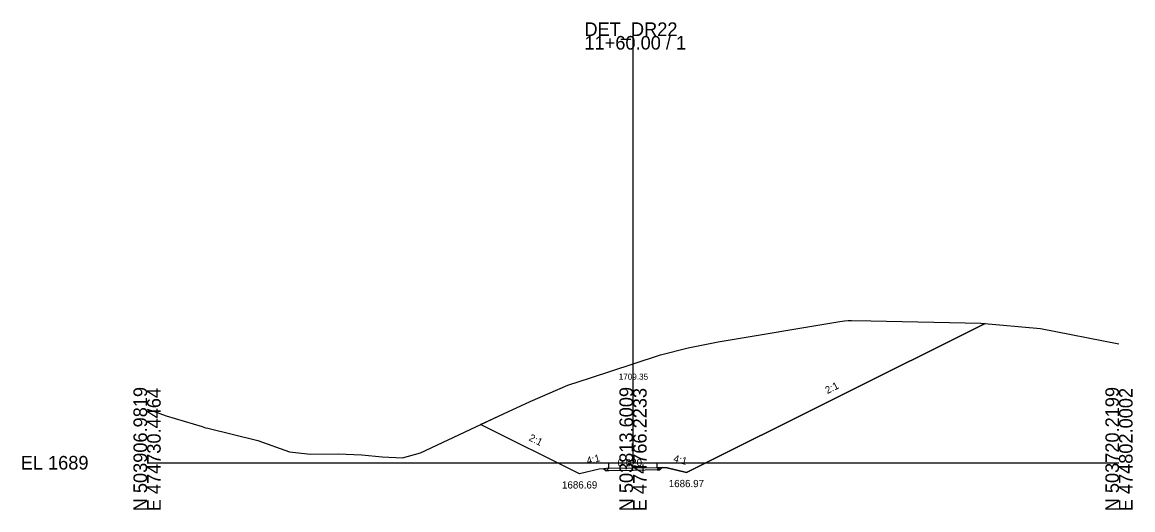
# Model space of a CAD drawing. Extents: x -26 to 1203, y -10 to 9633.
# Drawn here: x -25.7 to 202.8, y 3990.3 to 4090.7 of the extents above; entities that cross this region are included whole.
import ezdxf

# ---------------------------------------------------------------- set-up
doc = ezdxf.new("R2010")
doc.units = 0
for name, color, linetype in [('Exist Cross Section Cell', 7, 'Continuous'), ('Exist XS Center Line Elevation Label', 7, 'Continuous'), ('Exist XS Ground Line', 7, 'Continuous'), ('Prop XS Ditch Slope Text', 7, 'Continuous'), ('Prop XS Ditch Standard Text', 7, 'Continuous'), ('Prop XS Earthwork Shape', 7, 'Continuous'), ('Prop XS EOT Tick Mark', 7, 'Continuous'), ('Prop XS Finish Grade', 7, 'Continuous'), ('Prop XS Finish Grade Earthwork', 7, 'Continuous'), ('Prop XS Finish Grade Pavement', 7, 'Continuous'), ('Prop XS Pvmt Edge Slope', 7, 'Continuous'), ('Prop XS SE Text', 7, 'Continuous'), ('Prop XS Shoulder Borrow Shape', 7, 'Continuous'), ('Prop XS Side Slope Text', 7, 'Continuous'), ('Prop XS Subgrade Earthwork', 7, 'Continuous')]:
    doc.layers.add(name, color=color, linetype=linetype)

msp = doc.modelspace()

# ---------------------------------------------------------------- linework, layer by layer
at = {"layer": 'Exist Cross Section Cell'}
for p, q in [((100, 4000), (100, 4087.89)), ((0, 4000), (100, 4000)), ((100, 4000), (200, 4000))]:
    msp.add_line(p, q, dxfattribs=at)
at = {"layer": 'Exist XS Ground Line'}
msp.add_lwpolyline([(0, 4011.03), (1.34, 4010.61), (3.9, 4009.67), (11.33, 4007.45), (12.05, 4007.22), (12.5, 4007.1), (22.76, 4004.57), (29.32, 4002.26), (33.64, 4001.76), (39.29, 4001.86), (44.18, 4001.6), (48.37, 4001.21), (52.54, 4001.04), (56.3, 4002.07), (73.33, 4010.09), (78.86, 4012.58), (86.55, 4016), (91.28, 4017.51), (100, 4020.35), (105.62, 4022.19), (111.32, 4023.69), (117.54, 4024.89), (142.58, 4029.11), (143.51, 4029.24), (144.28, 4029.29), (144.93, 4029.3), (148.93, 4029.23), (171.6, 4028.77), (183.85, 4027.64), (200, 4024.48)], dxfattribs=at)
at = {"layer": 'Prop XS Earthwork Shape'}
msp.add_lwpolyline([(93, 3998.69), (89, 3997.69), (68.63, 4007.88), (73.33, 4010.09), (78.86, 4012.58), (86.55, 4016), (91.28, 4017.51), (100, 4020.35), (105.62, 4022.19), (111.32, 4023.69), (117.54, 4024.89), (142.58, 4029.11), (143.51, 4029.24), (144.28, 4029.29), (144.93, 4029.3), (148.93, 4029.23), (171.6, 4028.77), (172.44, 4028.69), (111, 3997.97), (107, 3998.97), (106.02, 3999.01), (105.53, 3998.52), (105, 3998.51), (100, 3998.41), (95, 3998.31), (94.45, 3998.3), (93.98, 3998.77)], close=True, dxfattribs=at)
at = {"layer": 'Prop XS EOT Tick Mark'}
for p, q in [((95, 3998.85), (95, 3999.85)), ((105, 3999.05), (105, 4000.05))]:
    msp.add_line(p, q, dxfattribs=at)
at = {"layer": 'Prop XS Finish Grade'}
for p, q in [((95, 3998.85), (93.98, 3998.77)), ((105, 3999.05), (106.02, 3999.01))]:
    msp.add_line(p, q, dxfattribs=at)
at = {"layer": 'Prop XS Finish Grade Earthwork'}
for p, q in [((111, 3997.97), (172.44, 4028.69)), ((89, 3997.69), (68.63, 4007.88)), ((93, 3998.69), (89, 3997.69)), ((93.98, 3998.77), (93, 3998.69)), ((106.02, 3999.01), (107, 3998.97)), ((107, 3998.97), (111, 3997.97))]:
    msp.add_line(p, q, dxfattribs=at)
at = {"layer": 'Prop XS Finish Grade Pavement'}
for p, q in [((95, 3998.85), (100, 3998.95)), ((100, 3998.95), (105, 3999.05))]:
    msp.add_line(p, q, dxfattribs=at)
at = {"layer": 'Prop XS Pvmt Edge Slope'}
for p, q in [((95, 3998.85), (94.45, 3998.3)), ((105, 3999.05), (105.53, 3998.52))]:
    msp.add_line(p, q, dxfattribs=at)
at = {"layer": 'Prop XS Shoulder Borrow Shape'}
for points in [[(95, 3998.85), (93.98, 3998.77), (94.45, 3998.3)], [(105, 3999.05), (106.02, 3999.01), (105.53, 3998.52)]]:
    msp.add_lwpolyline(points, close=True, dxfattribs=at)
at = {"layer": 'Prop XS Subgrade Earthwork'}
for p, q in [((94.45, 3998.3), (93.98, 3998.77)), ((95, 3998.31), (94.45, 3998.3)), ((100, 3998.41), (95, 3998.31)), ((105, 3998.51), (100, 3998.41)), ((105, 3998.51), (105.53, 3998.52)), ((105.53, 3998.52), (106.02, 3999.01))]:
    msp.add_line(p, q, dxfattribs=at)

# ---------------------------------------------------------------- texts
at = {"layer": 'Exist Cross Section Cell'}
for s, p in [('DET_DR22', (90, 4087.89)), ('11+60.00 / 1', (90, 4085.09)), ('EL 1689', (-26, 3998.6))]:
    msp.add_text(s, height=2.8, dxfattribs=at).set_placement(p)
for s, p in [('N 503906.9819', (0, 3990)), ('N 503813.6009', (100, 3990)), ('N 503720.2199', (200, 3990)), ('E 474730.4464', (2.8, 3990)), ('E 474766.2233', (102.8, 3990)), ('E 474802.0002', (202.8, 3990))]:
    msp.add_text(s, height=2.8, rotation=90, dxfattribs=at).set_placement(p)
at = {"layer": 'Exist XS Center Line Elevation Label'}
msp.add_text('1709.35', height=1.25, dxfattribs=at).set_placement((97.06, 4017.1))
at = {"layer": 'Prop XS Ditch Slope Text'}
for rotation, p in [(14.0362, (90.64, 3999.65)), (345.9638, (108.21, 4000.22))]:
    msp.add_text('4:1', height=1.5, rotation=rotation, dxfattribs=at).set_placement(p)
at = {"layer": 'Prop XS Ditch Standard Text'}
for s, p in [('1686.69', (85.39, 3994.69)), ('1686.97', (107.36, 3994.97))]:
    msp.add_text(s, height=1.5, dxfattribs=at).set_placement(p)
at = {"layer": 'Prop XS SE Text'}
msp.add_text('0.020', height=1.5, rotation=1.1458, dxfattribs=at).set_placement((96.85, 3999.21))
at = {"layer": 'Prop XS Side Slope Text'}
for rotation, p in [(26.5651, (139.99, 4014.14)), (333.4349, (78.42, 4004.66))]:
    msp.add_text('2:1', height=1.5, rotation=rotation, dxfattribs=at).set_placement(p)

doc.saveas('drawing.dxf')
